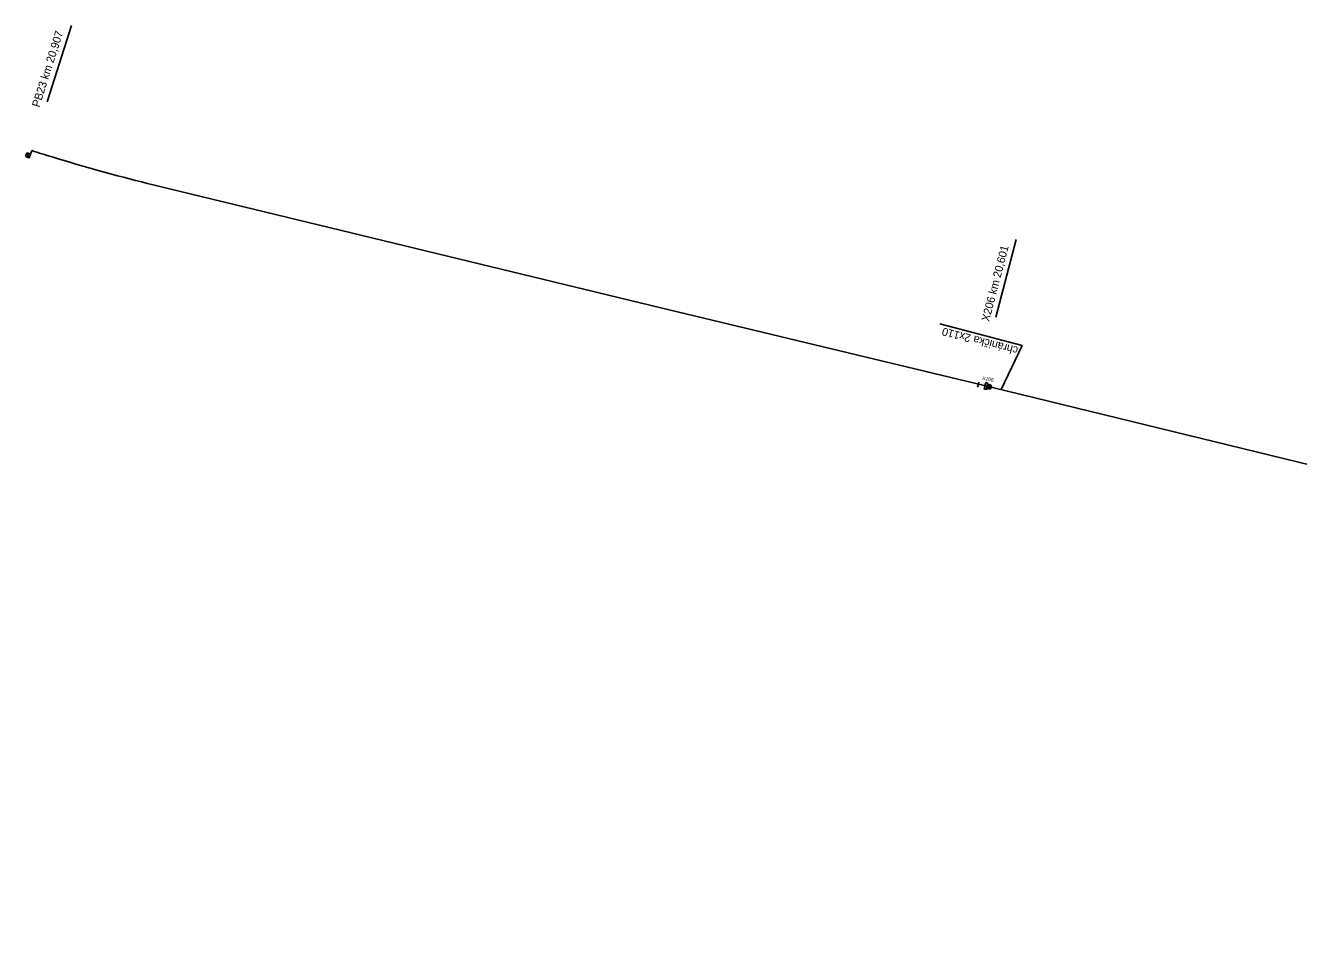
# Model space of a CAD drawing. Extents: x -748315 to -743169, y -1131781 to -1127091.
# Drawn here: x -748315.4 to -747917.7, y -1131774.4 to -1131488.9 of the extents above; entities that cross this region are included whole.
import ezdxf

# ---------------------------------------------------------------- set-up
doc = ezdxf.new("R2010")
doc.units = 0
for name, color, linetype in [('_Zabezpečovací zařízení', 7, 'Continuous'), ('_Zabezpečovací zařízení_trasa', 7, 'Continuous'), ('Nový stav', 7, 'Continuous')]:
    doc.layers.add(name, color=color, linetype=linetype)

msp = doc.modelspace()

# ---------------------------------------------------------------- linework, layer by layer
at = {"layer": '_Zabezpečovací zařízení'}
for p, q in [((-748314.99, -1131528.67), (-748315.37, -1131529.87)), ((-748315.37, -1131529.87), (-748314.18, -1131530.24)), ((-748313.8, -1131529.05), (-748314.99, -1131528.67)), ((-748314.77, -1131530.05), (-748314.4, -1131528.86)), ((-748314.18, -1131530.24), (-748313.8, -1131529.05)), ((-748017.87, -1131601.61), (-748017.55, -1131600.27)), ((-748017.71, -1131600.94), (-748015.04, -1131601.59))]:
    msp.add_line(p, q, dxfattribs=at)
msp.add_lwpolyline([(-748313.8, -1131529.05), (-748314.4, -1131528.86), (-748314.77, -1131530.05), (-748314.18, -1131530.24), (-748313.8, -1131529.05)], dxfattribs=at)
msp.add_lwpolyline([(-748015.46, -1131600.43), (-748014.8, -1131600.59), (-748015.28, -1131602.59), (-748015.95, -1131602.43)], close=True, dxfattribs=at)
for radius in [0.687, 0.481]:
    msp.add_circle((-748014.37, -1131601.75), radius, dxfattribs=at)
at = {"layer": '_Zabezpečovací zařízení_trasa'}
for p, q in [((-748313.42, -1131527.99), (-748314.18, -1131530.24)), ((-748017.71, -1131600.94), (-748017.97, -1131601.88))]:
    msp.add_line(p, q, dxfattribs=at)
msp.add_lwpolyline([(-747299.39, -1131774.36), (-747312.96, -1131771.54), (-747335.19, -1131765.86), (-747431.5, -1131743.03), (-747485.59, -1131729.82), (-747529.87, -1131718.9), (-747616.75, -1131698.31), (-747822.02, -1131648.41), (-747861.48, -1131639.04), (-748013.3, -1131602), (-748116.9, -1131577.08), (-748210.22, -1131554.48), (-748277.3, -1131538.23)], dxfattribs=at)
for centre, radius, start, end in [((-748154.06, -1131026.42), 526.28, 252.3739, 253.1036), ((-748140.25, -1130986.72), 568.28, 252.9343, 256.0443)]:
    msp.add_arc(centre, radius, start, end, dxfattribs=at)
at = {"layer": 'Nový stav'}
for p, q in [((-748308.61, -1131512.74), (-748301.04, -1131488.92)), ((-748012.26, -1131579.98), (-748005.96, -1131555.78)), ((-748004.08, -1131588.86), (-748029.73, -1131582.14)), ((-748010.64, -1131602.55), (-748004.08, -1131588.86))]:
    msp.add_line(p, q, dxfattribs=at)

# ---------------------------------------------------------------- texts
at = {"layer": '_Zabezpečovací zařízení'}
msp.add_text('X206', height=1.1, rotation=348.4035, dxfattribs=at).set_placement((-748016.55, -1131599.5))
at = {"layer": 'Nový stav'}
for s, rotation, p in [('PB23 km 20,907', 72.3713, (-748311.04, -1131514.64)), ('X206 km 20,601', 75.402, (-748014.39, -1131581.52)), ('chránička 2x110', 165.3169, (-748005.16, -1131589.37))]:
    msp.add_text(s, height=2.5, rotation=rotation, dxfattribs=at).set_placement(p)

doc.saveas('drawing.dxf')
